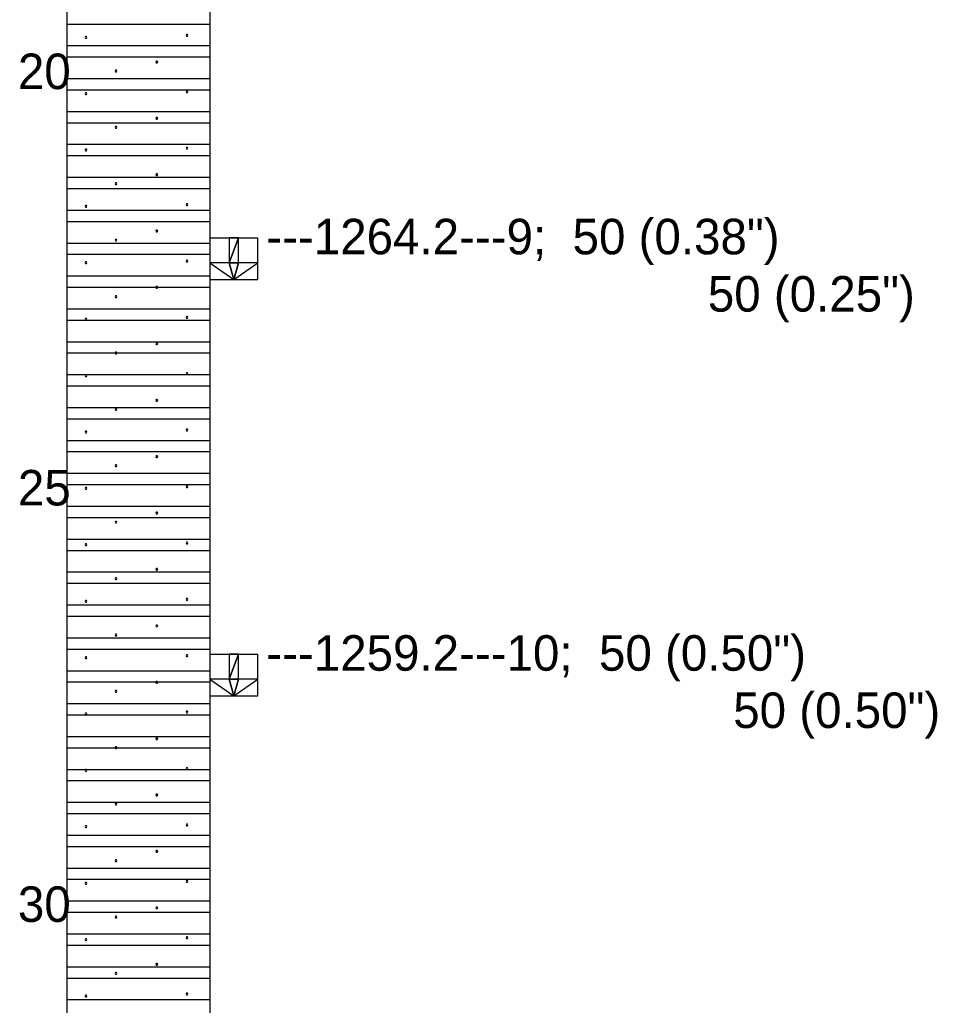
# Model space of a CAD drawing. Extents: x -6 to 173, y 24 to 64.
# Drawn here: x 18.142 to 21.344, y 40.318 to 43.758 of the extents above; entities that cross this region are included whole.
import ezdxf

# ---------------------------------------------------------------- set-up
doc = ezdxf.new("R2010")
doc.units = 0

msp = doc.modelspace()

# ---------------------------------------------------------------- linework, layer by layer
for points in [[(18.3057, 49.3922), (18.3057, 37.1829)], [(18.8057, 49.3922), (18.8057, 37.1829)], [(18.3057, 43.7434), (18.8057, 43.7434)], [(18.3761, 43.6973), (18.3744, 43.7001), (18.3711, 43.7001), (18.3695, 43.6973), (18.3711, 43.6944), (18.3744, 43.6944), (18.3761, 43.6973)], [(18.7288, 43.7037), (18.7272, 43.7066), (18.7239, 43.7066), (18.7223, 43.7037), (18.7239, 43.7009), (18.7272, 43.7009), (18.7288, 43.7037)], [(18.3057, 43.668), (18.8057, 43.668)], [(18.3057, 43.6286), (18.8057, 43.6286)], [(18.6233, 43.6112), (18.6217, 43.614), (18.6184, 43.614), (18.6167, 43.6112), (18.6184, 43.6084), (18.6217, 43.6084), (18.6233, 43.6112)], [(18.3057, 43.5532), (18.8057, 43.5532)], [(18.4807, 43.5793), (18.4791, 43.5822), (18.4758, 43.5822), (18.4742, 43.5794), (18.4758, 43.5765), (18.4791, 43.5765), (18.4807, 43.5793)], [(18.3057, 43.5138), (18.8057, 43.5138)], [(18.3761, 43.5004), (18.3744, 43.5032), (18.3711, 43.5032), (18.3695, 43.5004), (18.3711, 43.4975), (18.3744, 43.4975), (18.3761, 43.5004)], [(18.7288, 43.5069), (18.7272, 43.5098), (18.7239, 43.5098), (18.7223, 43.5069), (18.7239, 43.5041), (18.7272, 43.5041), (18.7288, 43.5069)], [(18.3057, 43.4383), (18.8057, 43.4383)], [(18.6233, 43.4144), (18.6217, 43.4172), (18.6184, 43.4172), (18.6167, 43.4144), (18.6184, 43.4116), (18.6217, 43.4116), (18.6233, 43.4144)], [(18.3057, 43.399), (18.8057, 43.399)], [(18.4807, 43.3825), (18.4791, 43.3854), (18.4758, 43.3854), (18.4742, 43.3826), (18.4758, 43.3797), (18.4791, 43.3797), (18.4807, 43.3825)], [(18.3057, 43.3235), (18.8057, 43.3235)], [(18.7288, 43.31), (18.7272, 43.3129), (18.7239, 43.3129), (18.7223, 43.31), (18.7239, 43.3072), (18.7272, 43.3072), (18.7288, 43.31)], [(18.3057, 43.2841), (18.8057, 43.2841)], [(18.3761, 43.3036), (18.3744, 43.3064), (18.3711, 43.3064), (18.3695, 43.3036), (18.3711, 43.3007), (18.3744, 43.3007), (18.3761, 43.3036)], [(18.3057, 43.2087), (18.8057, 43.2087)], [(18.6233, 43.2175), (18.6217, 43.2203), (18.6184, 43.2203), (18.6167, 43.2175), (18.6184, 43.2147), (18.6217, 43.2147), (18.6233, 43.2175)], [(18.4807, 43.1856), (18.4791, 43.1885), (18.4758, 43.1885), (18.4742, 43.1857), (18.4758, 43.1828), (18.4791, 43.1828), (18.4807, 43.1856)], [(18.3057, 43.1693), (18.8057, 43.1693)], [(18.3761, 43.1067), (18.3744, 43.1095), (18.3711, 43.1095), (18.3695, 43.1067), (18.3711, 43.1038), (18.3744, 43.1038), (18.3761, 43.1067)], [(18.7288, 43.1132), (18.7272, 43.1161), (18.7239, 43.1161), (18.7223, 43.1132), (18.7239, 43.1104), (18.7272, 43.1104), (18.7288, 43.1132)], [(18.3057, 43.0938), (18.8057, 43.0938)], [(18.3057, 43.0545), (18.8057, 43.0545)], [(18.6233, 43.0207), (18.6217, 43.0235), (18.6184, 43.0235), (18.6167, 43.0207), (18.6184, 43.0179), (18.6217, 43.0179), (18.6233, 43.0207)], [(18.3057, 42.979), (18.8057, 42.979)], [(18.4807, 42.9888), (18.4791, 42.9917), (18.4758, 42.9917), (18.4742, 42.9889), (18.4758, 42.986), (18.4791, 42.986), (18.4807, 42.9888)], [(18.8057, 42.9968), (18.9723, 42.9968)], [(18.9723, 42.8515), (18.9723, 42.9968)], [(18.3057, 42.9396), (18.8057, 42.9396)], [(18.3761, 42.9098), (18.3744, 42.9127), (18.3711, 42.9127), (18.3695, 42.9098), (18.3711, 42.907), (18.3744, 42.907), (18.3761, 42.9098)], [(18.7288, 42.9163), (18.7272, 42.9192), (18.7239, 42.9192), (18.7223, 42.9163), (18.7239, 42.9135), (18.7272, 42.9135), (18.7288, 42.9163)], [(18.3057, 42.8642), (18.8057, 42.8642)], [(18.8057, 42.8515), (18.9723, 42.8515)], [(18.3057, 42.8248), (18.8057, 42.8248)], [(18.6233, 42.8238), (18.6217, 42.8266), (18.6184, 42.8266), (18.6167, 42.8238), (18.6184, 42.821), (18.6217, 42.821), (18.6233, 42.8238)], [(18.4807, 42.7919), (18.4791, 42.7948), (18.4758, 42.7948), (18.4742, 42.792), (18.4758, 42.7891), (18.4791, 42.7891), (18.4807, 42.7919)], [(18.3057, 42.7494), (18.8057, 42.7494)], [(18.3057, 42.71), (18.8057, 42.71)], [(18.3761, 42.713), (18.3744, 42.7158), (18.3711, 42.7158), (18.3695, 42.713), (18.3711, 42.7101), (18.3744, 42.7101), (18.3761, 42.713)], [(18.7288, 42.7195), (18.7272, 42.7224), (18.7239, 42.7224), (18.7223, 42.7195), (18.7239, 42.7167), (18.7272, 42.7167), (18.7288, 42.7195)], [(18.3057, 42.6345), (18.8057, 42.6345)], [(18.6233, 42.627), (18.6217, 42.6298), (18.6184, 42.6298), (18.6167, 42.627), (18.6184, 42.6242), (18.6217, 42.6242), (18.6233, 42.627)], [(18.3057, 42.5952), (18.8057, 42.5952)], [(18.4807, 42.5951), (18.4791, 42.598), (18.4758, 42.598), (18.4742, 42.5952), (18.4758, 42.5923), (18.4791, 42.5923), (18.4807, 42.5951)], [(18.7288, 42.5226), (18.7272, 42.5255), (18.7239, 42.5255), (18.7223, 42.5226), (18.7239, 42.5198), (18.7272, 42.5198), (18.7288, 42.5226)], [(18.3057, 42.5197), (18.8057, 42.5197)], [(18.3761, 42.5161), (18.3744, 42.519), (18.3711, 42.519), (18.3695, 42.5161), (18.3711, 42.5133), (18.3744, 42.5133), (18.3761, 42.5161)], [(18.3057, 42.4803), (18.8057, 42.4803)], [(18.6233, 42.4301), (18.6217, 42.4329), (18.6184, 42.4329), (18.6167, 42.4301), (18.6184, 42.4273), (18.6217, 42.4273), (18.6233, 42.4301)], [(18.3057, 42.4049), (18.8057, 42.4049)], [(18.4807, 42.3982), (18.4791, 42.4011), (18.4758, 42.4011), (18.4742, 42.3983), (18.4758, 42.3954), (18.4791, 42.3954), (18.4807, 42.3982)], [(18.3057, 42.3655), (18.8057, 42.3655)], [(18.3761, 42.3193), (18.3744, 42.3221), (18.3711, 42.3221), (18.3695, 42.3193), (18.3711, 42.3164), (18.3744, 42.3164), (18.3761, 42.3193)], [(18.7288, 42.3258), (18.7272, 42.3287), (18.7239, 42.3287), (18.7223, 42.3258), (18.7239, 42.323), (18.7272, 42.323), (18.7288, 42.3258)], [(18.3057, 42.29), (18.8057, 42.29)], [(18.3057, 42.2507), (18.8057, 42.2507)], [(18.6233, 42.2333), (18.6217, 42.2361), (18.6184, 42.2361), (18.6167, 42.2333), (18.6184, 42.2305), (18.6217, 42.2305), (18.6233, 42.2333)], [(18.4807, 42.2014), (18.4791, 42.2043), (18.4758, 42.2043), (18.4742, 42.2015), (18.4758, 42.1986), (18.4791, 42.1986), (18.4807, 42.2014)], [(18.3057, 42.1752), (18.8057, 42.1752)], [(18.3057, 42.1358), (18.8057, 42.1358)], [(18.3761, 42.1224), (18.3744, 42.1253), (18.3711, 42.1253), (18.3695, 42.1224), (18.3711, 42.1196), (18.3744, 42.1196), (18.3761, 42.1224)], [(18.7288, 42.1289), (18.7272, 42.1318), (18.7239, 42.1318), (18.7223, 42.1289), (18.7239, 42.1261), (18.7272, 42.1261), (18.7288, 42.1289)], [(18.3057, 42.0604), (18.8057, 42.0604)], [(18.6233, 42.0364), (18.6217, 42.0392), (18.6184, 42.0392), (18.6167, 42.0364), (18.6184, 42.0336), (18.6217, 42.0336), (18.6233, 42.0364)], [(18.3057, 42.021), (18.8057, 42.021)], [(18.4807, 42.0045), (18.4791, 42.0074), (18.4758, 42.0074), (18.4742, 42.0046), (18.4758, 42.0017), (18.4791, 42.0017), (18.4807, 42.0045)], [(18.3057, 41.9455), (18.8057, 41.9455)], [(18.3057, 41.9062), (18.8057, 41.9062)], [(18.3761, 41.9256), (18.3744, 41.9284), (18.3711, 41.9284), (18.3695, 41.9256), (18.3711, 41.9227), (18.3744, 41.9227), (18.3761, 41.9256)], [(18.7288, 41.9321), (18.7272, 41.935), (18.7239, 41.935), (18.7223, 41.9321), (18.7239, 41.9293), (18.7272, 41.9293), (18.7288, 41.9321)], [(18.6233, 41.8396), (18.6217, 41.8424), (18.6184, 41.8424), (18.6167, 41.8396), (18.6184, 41.8368), (18.6217, 41.8368), (18.6233, 41.8396)], [(18.3057, 41.8307), (18.8057, 41.8307)], [(18.4807, 41.8077), (18.4791, 41.8106), (18.4758, 41.8106), (18.4742, 41.8077), (18.4758, 41.8049), (18.4791, 41.8049), (18.4807, 41.8077)], [(18.3057, 41.7913), (18.8057, 41.7913)], [(18.3761, 41.7287), (18.3744, 41.7316), (18.3711, 41.7316), (18.3695, 41.7287), (18.3711, 41.7259), (18.3744, 41.7259), (18.3761, 41.7287)], [(18.7288, 41.7352), (18.7272, 41.7381), (18.7239, 41.7381), (18.7223, 41.7352), (18.7239, 41.7324), (18.7272, 41.7324), (18.7288, 41.7352)], [(18.3057, 41.7159), (18.8057, 41.7159)], [(18.3057, 41.6765), (18.8057, 41.6765)], [(18.6233, 41.6427), (18.6217, 41.6455), (18.6184, 41.6455), (18.6167, 41.6427), (18.6184, 41.6399), (18.6217, 41.6399), (18.6233, 41.6427)], [(18.3057, 41.6011), (18.8057, 41.6011)], [(18.4807, 41.6108), (18.4791, 41.6137), (18.4758, 41.6137), (18.4742, 41.6109), (18.4758, 41.608), (18.4791, 41.608), (18.4807, 41.6108)], [(18.3057, 41.5617), (18.8057, 41.5617)], [(18.3761, 41.5319), (18.3744, 41.5347), (18.3711, 41.5347), (18.3695, 41.5319), (18.3711, 41.529), (18.3744, 41.529), (18.3761, 41.5319)], [(18.7288, 41.5384), (18.7272, 41.5413), (18.7239, 41.5413), (18.7223, 41.5384), (18.7239, 41.5356), (18.7272, 41.5356), (18.7288, 41.5384)], [(18.8057, 41.5434), (18.9723, 41.5434)], [(18.9723, 41.398), (18.9723, 41.5434)], [(18.3057, 41.4862), (18.8057, 41.4862)], [(18.3057, 41.4469), (18.8057, 41.4469)], [(18.6233, 41.4459), (18.6217, 41.4487), (18.6184, 41.4487), (18.6167, 41.4459), (18.6184, 41.4431), (18.6217, 41.4431), (18.6233, 41.4459)], [(18.4807, 41.414), (18.4791, 41.4169), (18.4758, 41.4169), (18.4742, 41.414), (18.4758, 41.4112), (18.4791, 41.4112), (18.4807, 41.414)], [(18.8057, 41.398), (18.9723, 41.398)], [(18.3057, 41.3714), (18.8057, 41.3714)], [(18.3057, 41.332), (18.8057, 41.332)], [(18.3761, 41.335), (18.3744, 41.3379), (18.3711, 41.3379), (18.3695, 41.335), (18.3711, 41.3322), (18.3744, 41.3322), (18.3761, 41.335)], [(18.7288, 41.3415), (18.7272, 41.3444), (18.7239, 41.3444), (18.7223, 41.3415), (18.7239, 41.3387), (18.7272, 41.3387), (18.7288, 41.3415)], [(18.3057, 41.2566), (18.8057, 41.2566)], [(18.6233, 41.249), (18.6217, 41.2518), (18.6184, 41.2518), (18.6167, 41.249), (18.6184, 41.2462), (18.6217, 41.2462), (18.6233, 41.249)], [(18.3057, 41.2172), (18.8057, 41.2172)], [(18.4807, 41.2171), (18.4791, 41.22), (18.4758, 41.22), (18.4742, 41.2172), (18.4758, 41.2143), (18.4791, 41.2143), (18.4807, 41.2171)], [(18.7288, 41.1447), (18.7272, 41.1476), (18.7239, 41.1476), (18.7223, 41.1447), (18.7239, 41.1419), (18.7272, 41.1419), (18.7288, 41.1447)], [(18.3057, 41.1417), (18.8057, 41.1417)], [(18.3761, 41.1382), (18.3744, 41.141), (18.3711, 41.141), (18.3695, 41.1382), (18.3711, 41.1353), (18.3744, 41.1353), (18.3761, 41.1382)], [(18.3057, 41.1024), (18.8057, 41.1024)], [(18.6233, 41.0522), (18.6217, 41.055), (18.6184, 41.055), (18.6167, 41.0522), (18.6184, 41.0494), (18.6217, 41.0494), (18.6233, 41.0522)], [(18.3057, 41.0269), (18.8057, 41.0269)], [(18.4807, 41.0203), (18.4791, 41.0232), (18.4758, 41.0232), (18.4742, 41.0203), (18.4758, 41.0175), (18.4791, 41.0175), (18.4807, 41.0203)], [(18.3057, 40.9875), (18.8057, 40.9875)], [(18.3761, 40.9413), (18.3744, 40.9442), (18.3711, 40.9442), (18.3695, 40.9413), (18.3711, 40.9385), (18.3744, 40.9385), (18.3761, 40.9413)], [(18.7288, 40.9478), (18.7272, 40.9507), (18.7239, 40.9507), (18.7223, 40.9478), (18.7239, 40.945), (18.7272, 40.945), (18.7288, 40.9478)], [(18.3057, 40.9121), (18.8057, 40.9121)], [(18.3057, 40.8727), (18.8057, 40.8727)], [(18.6233, 40.8553), (18.6217, 40.8581), (18.6184, 40.8581), (18.6167, 40.8553), (18.6184, 40.8525), (18.6217, 40.8525), (18.6233, 40.8553)], [(18.4807, 40.8234), (18.4791, 40.8263), (18.4758, 40.8263), (18.4742, 40.8235), (18.4758, 40.8206), (18.4791, 40.8206), (18.4807, 40.8234)], [(18.3057, 40.7973), (18.8057, 40.7973)], [(18.3057, 40.7579), (18.8057, 40.7579)], [(18.3761, 40.7445), (18.3744, 40.7473), (18.3711, 40.7473), (18.3695, 40.7445), (18.3711, 40.7416), (18.3744, 40.7416), (18.3761, 40.7445)], [(18.7288, 40.751), (18.7272, 40.7539), (18.7239, 40.7539), (18.7223, 40.751), (18.7239, 40.7482), (18.7272, 40.7482), (18.7288, 40.751)], [(18.3057, 40.6824), (18.8057, 40.6824)], [(18.3057, 40.6431), (18.8057, 40.6431)], [(18.4807, 40.6266), (18.4791, 40.6295), (18.4758, 40.6295), (18.4742, 40.6266), (18.4758, 40.6238), (18.4791, 40.6238), (18.4807, 40.6266)], [(18.6233, 40.6585), (18.6217, 40.6613), (18.6184, 40.6613), (18.6167, 40.6585), (18.6184, 40.6556), (18.6217, 40.6556), (18.6233, 40.6585)], [(18.3057, 40.5676), (18.8057, 40.5676)], [(18.3057, 40.5282), (18.8057, 40.5282)], [(18.3761, 40.5476), (18.3744, 40.5505), (18.3711, 40.5505), (18.3695, 40.5476), (18.3711, 40.5448), (18.3744, 40.5448), (18.3761, 40.5476)], [(18.7288, 40.5541), (18.7272, 40.557), (18.7239, 40.557), (18.7223, 40.5541), (18.7239, 40.5513), (18.7272, 40.5513), (18.7288, 40.5541)], [(18.6233, 40.4616), (18.6217, 40.4644), (18.6184, 40.4644), (18.6167, 40.4616), (18.6184, 40.4588), (18.6217, 40.4588), (18.6233, 40.4616)], [(18.3057, 40.4528), (18.8057, 40.4528)], [(18.4807, 40.4297), (18.4791, 40.4326), (18.4758, 40.4326), (18.4742, 40.4298), (18.4758, 40.4269), (18.4791, 40.4269), (18.4807, 40.4297)], [(18.3057, 40.4134), (18.8057, 40.4134)], [(18.3761, 40.3508), (18.3744, 40.3536), (18.3711, 40.3536), (18.3695, 40.3508), (18.3711, 40.3479), (18.3744, 40.3479), (18.3761, 40.3508)], [(18.7288, 40.3573), (18.7272, 40.3602), (18.7239, 40.3602), (18.7223, 40.3573), (18.7239, 40.3545), (18.7272, 40.3545), (18.7288, 40.3573)], [(18.3057, 40.3379), (18.8057, 40.3379)]]:
    msp.add_lwpolyline(points)
for points in [[(18.8723, 42.9096), (18.9057, 42.9096), (18.9057, 42.9968), (18.8723, 42.9096)], [(18.8723, 42.9096), (18.9057, 42.9968), (18.8723, 42.9968), (18.8723, 42.9096)], [(18.8723, 42.9096), (18.8057, 42.9096), (18.889, 42.8515), (18.8723, 42.9096)], [(18.8723, 42.9096), (18.889, 42.8515), (18.9057, 42.9096), (18.8723, 42.9096)], [(18.889, 42.8515), (18.9723, 42.9096), (18.9057, 42.9096), (18.889, 42.8515)], [(18.8723, 41.4562), (18.9057, 41.4562), (18.9057, 41.5434), (18.8723, 41.4562)], [(18.8723, 41.4562), (18.9057, 41.5434), (18.8723, 41.5434), (18.8723, 41.4562)], [(18.8723, 41.4562), (18.8057, 41.4562), (18.889, 41.398), (18.8723, 41.4562)], [(18.8723, 41.4562), (18.889, 41.398), (18.9057, 41.4562), (18.8723, 41.4562)], [(18.889, 41.398), (18.9723, 41.4562), (18.9057, 41.4562), (18.889, 41.398)]]:
    msp.add_lwpolyline(points, close=True)

# ---------------------------------------------------------------- texts
for s, p in [('20', (18.1352, 43.5162)), ('---1264.2---9;  50 (0.38")', (19.0024, 42.9395)), ('50 (0.25")', (20.5434, 42.7395)), ('25', (18.1352, 42.0628)), ('---1259.2---10;  50 (0.50")', (19.0024, 41.4861)), ('50 (0.50")', (20.6321, 41.2861)), ('30', (18.1352, 40.6093))]:
    msp.add_text(s, height=0.124).set_placement(p)

doc.saveas('drawing.dxf')
